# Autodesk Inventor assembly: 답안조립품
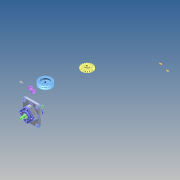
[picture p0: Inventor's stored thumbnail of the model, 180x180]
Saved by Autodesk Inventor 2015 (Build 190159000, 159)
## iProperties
Created: 2026-07
Part Number: 답안조립품
Document SubType Name: Assembly
Designer: USER
Author: USER
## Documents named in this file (12)
- C:\Users\USER\Desktop\760705V1008\답안조립품.iam
- C:\Users\USER\Desktop\760705V1008\본체.ipt
- C:\Users\USER\Desktop\760705V1008\가져온 구성요소\6각 구멍붙이 볼트 M6x16\6각 구멍붙이 볼트 M6x16.ipt
- C:\Users\USER\Desktop\760705V1008\가져온 구성요소\6각 플랜지 너트 M16\6각 플랜지 너트 M16.ipt
- C:\Users\USER\Desktop\760705V1008\가져온 구성요소\V-벨트풀리\V-벨트풀리.ipt
- C:\Users\USER\Desktop\760705V1008\가져온 구성요소\깊은 홈 볼 베어링 6206\깊은 홈 볼 베어링 6206.ipt
- C:\Users\USER\Desktop\760705V1008\가져온 구성요소\오일 실 30 45 8\오일 실 30 45 8.ipt
- C:\Users\USER\Desktop\760705V1008\가져온 구성요소\체인 스프로킷\체인 스프로킷.ipt
- C:\Users\USER\Desktop\760705V1008\가져온 구성요소\축\축.ipt
- C:\Users\USER\Desktop\760705V1008\가져온 구성요소\칼라\칼라.ipt
- C:\Users\USER\Desktop\760705V1008\가져온 구성요소\커버\커버.ipt
- C:\Users\USER\Desktop\760705V1008\가져온 구성요소\평행 키 6x6x20\평행 키 6x6x20.ipt
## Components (11 placed, 3 different names)
1. 6각 구멍붙이 볼트 M6x16:1
2. 6각 플랜지 너트 M16:1
3. V-벨트풀리:1
4. 6각 플랜지 너트 M16:2
5. 6각 구멍붙이 볼트 M6x16:2
6. 6각 구멍붙이 볼트 M6x16:3
7. 6각 구멍붙이 볼트 M6x16:4
8. 6각 구멍붙이 볼트 M6x16:5
9. 6각 구멍붙이 볼트 M6x16:6
10. 6각 구멍붙이 볼트 M6x16:7
11. 6각 구멍붙이 볼트 M6x16:8
